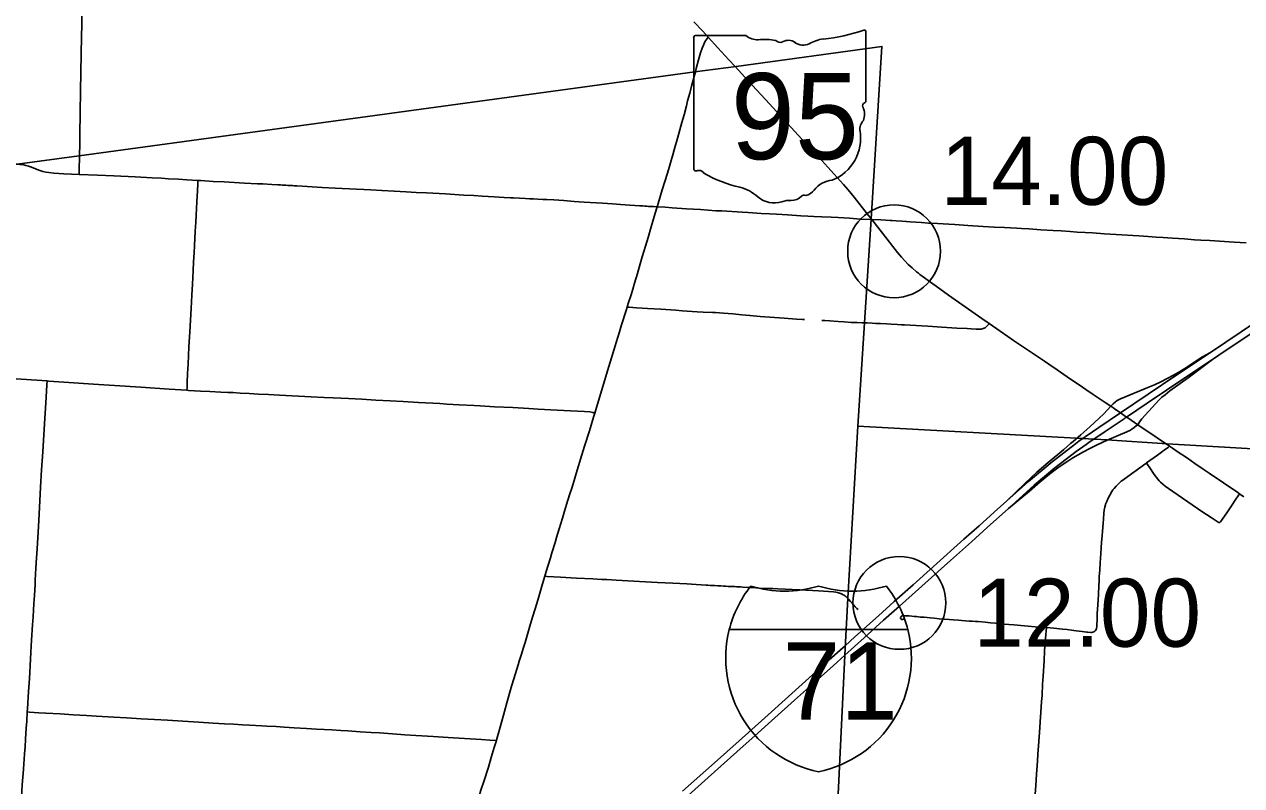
# Model space of a CAD drawing. Extents: x 1813937 to 1948437, y 826606 to 1022856.
# Drawn here: x 1890191 to 1909861, y 903518 to 915824 of the extents above; entities that cross this region are included whole.
import ezdxf

# ---------------------------------------------------------------- set-up
doc = ezdxf.new("R2010")
doc.units = 0
for name, color, linetype in [('Default', 7, 'Continuous'), ('GM_X_County_Road', 7, 'Continuous'), ('GM_X_Interchange_Ramps', 7, 'Continuous'), ('GM_X_Interstate_Route', 7, 'Continuous'), ('GM_X_Interstate_Shield', 7, 'Continuous'), ('GM_X_State_Route', 7, 'Continuous'), ('GM_X_State_Shield', 7, 'Continuous'), ('GM_X_Township', 7, 'Continuous'), ('GM_X_Township_Road', 7, 'Continuous')]:
    doc.layers.add(name, color=color, linetype=linetype)

msp = doc.modelspace()

# ---------------------------------------------------------------- linework, layer by layer
at = {"layer": 'Default'}
for centre in [(1904245, 912156), (1904331, 906472)]:
    msp.add_circle(centre, 750, dxfattribs=at)
at = {"layer": 'GM_X_County_Road'}
for points in [[(1901034, 915058), (1901047, 915109), (1901087, 915251), (1901119, 915361), (1901146, 915439), (1901163, 915485), (1901184, 915530), (1901200, 915558), (1901213, 915580), (1901223, 915594), (1901241, 915616)], [(1900416, 912874), (1900432, 912930), (1900499, 913150), (1900581, 913417), (1900609, 913511), (1900642, 913621), (1900670, 913715), (1900692, 913794), (1900751, 913999), (1900817, 914236), (1900852, 914363), (1900889, 914506), (1900909, 914585), (1900943, 914712), (1900972, 914823), (1901013, 914982), (1901034, 915058)], [(1899931, 911252), (1899950, 911310), (1899994, 911451), (1900023, 911545), (1900051, 911640), (1900097, 911797), (1900144, 911955), (1900176, 912065), (1900227, 912238), (1900269, 912379), (1900321, 912552), (1900386, 912773), (1900416, 912874)], [(1903887, 912667), (1904032, 912662), (1904114, 912658), (1904180, 912653), (1904212, 912651), (1904280, 912647), (1904372, 912640), (1904440, 912636), (1904445, 912636)], [(1904445, 912636), (1904506, 912632), (1904686, 912620), (1904800, 912612), (1904948, 912603), (1905128, 912592), (1905226, 912587), (1905439, 912573), (1905684, 912559), (1905864, 912548), (1906028, 912539), (1906224, 912528), (1906306, 912524), (1906421, 912516), (1906617, 912503), (1906813, 912493), (1906942, 912486), (1907089, 912475), (1907204, 912467), (1907334, 912460), (1907449, 912453), (1907645, 912440), (1907923, 912420), (1908103, 912409), (1908202, 912403), (1908349, 912393), (1908480, 912385), (1908594, 912377), (1908741, 912367), (1908938, 912355), (1909101, 912343), (1909199, 912338), (1909347, 912329), (1909740, 912304), (1909936, 912291)], [(1899410, 909541), (1899437, 909631), (1899637, 910291), (1899723, 910574), (1899756, 910684), (1899809, 910856), (1899843, 910966), (1899915, 911201), (1899931, 911252)], [(1887573, 910239), (1887606, 910237), (1887655, 910234), (1887786, 910225), (1887982, 910215), (1888179, 910203), (1888392, 910190), (1888850, 910163), (1889128, 910146), (1889390, 910131), (1889620, 910119), (1889849, 910105), (1890061, 910092), (1890307, 910076), (1890560, 910061)], [(1890238, 904709), (1890241, 904759), (1890260, 905038), (1890272, 905250), (1890290, 905561), (1890297, 905676), (1890309, 905872), (1890323, 906118), (1890332, 906249), (1890346, 906461), (1890354, 906592), (1890364, 906772), (1890368, 906838), (1890379, 907034), (1890389, 907199), (1890398, 907345), (1890418, 907705), (1890435, 908016), (1890455, 908343), (1890469, 908622), (1890488, 908916), (1890523, 909456), (1890533, 909620), (1890543, 909800), (1890556, 909996), (1890560, 910061)], [(1890560, 910061), (1890585, 910059), (1890831, 910042), (1891387, 910005), (1891649, 909988), (1892074, 909958), (1892532, 909928), (1892818, 909909)], [(1892818, 909909), (1892843, 909907), (1893040, 909896), (1893187, 909888), (1893367, 909879), (1893482, 909874), (1893563, 909871), (1893678, 909865), (1893825, 909857), (1893973, 909848), (1894136, 909840), (1894316, 909831), (1894824, 909804), (1895037, 909794), (1895184, 909787), (1895430, 909774), (1895643, 909764), (1895872, 909750), (1896101, 909737), (1896314, 909726), (1896560, 909712), (1896904, 909694), (1897018, 909687), (1897215, 909676), (1897460, 909664), (1897558, 909659), (1897788, 909644), (1898082, 909628), (1898344, 909614), (1898492, 909606), (1898803, 909589), (1899016, 909578), (1899245, 909566), (1899326, 909558), (1899375, 909552), (1899410, 909541)], [(1898602, 906902), (1898625, 906980), (1898691, 907200), (1898715, 907279), (1898769, 907451), (1898792, 907529), (1898835, 907671), (1898888, 907843), (1898921, 907953), (1898954, 908063), (1899002, 908220), (1899041, 908345), (1899085, 908487), (1899109, 908565), (1899201, 908863), (1899244, 909004), (1899322, 909255), (1899390, 909474), (1899410, 909541)], [(1908324, 908735), (1908499, 908861), (1908633, 908955), (1908672, 908985), (1908697, 909005)], [(1907661, 908057), (1907663, 908066), (1907680, 908112), (1907700, 908156), (1907729, 908215), (1907762, 908271), (1907780, 908298), (1907800, 908323), (1907833, 908360), (1907868, 908394), (1907916, 908438), (1907941, 908458), (1908021, 908516), (1908313, 908727), (1908324, 908735)], [(1908324, 908735), (1908339, 908712), (1908375, 908657), (1908450, 908550), (1908509, 908471), (1908529, 908446), (1908551, 908422), (1908587, 908389), (1908624, 908358), (1908677, 908320), (1909220, 907952), (1909369, 907850), (1909483, 907775), (1909492, 907771), (1909501, 907770)], [(1909501, 907770), (1909510, 907774), (1909517, 907781), (1909621, 907930), (1909695, 908039), (1909769, 908148), (1909805, 908204), (1909826, 908236)], [(1907528, 906301), (1907531, 906370), (1907541, 906518), (1907547, 906616), (1907554, 906746), (1907559, 906828), (1907561, 906894), (1907568, 907008), (1907576, 907122), (1907586, 907269), (1907593, 907368), (1907598, 907449), (1907607, 907563), (1907611, 907629), (1907621, 907759), (1907626, 907825), (1907635, 907922), (1907641, 907971), (1907651, 908019), (1907661, 908057)], [(1897819, 904246), (1897828, 904274), (1897881, 904463), (1897949, 904717), (1897988, 904859), (1898045, 905065), (1898068, 905143), (1898126, 905331), (1898170, 905473), (1898188, 905530), (1898219, 905629), (1898259, 905754), (1898282, 905833), (1898370, 906132), (1898408, 906258), (1898470, 906462), (1898498, 906556), (1898555, 906744), (1898597, 906886), (1898602, 906902)], [(1898602, 906902), (1898640, 906899), (1898853, 906887), (1899114, 906873), (1899376, 906859), (1899524, 906852), (1899605, 906848), (1899752, 906839), (1899851, 906833), (1900129, 906818), (1900423, 906802), (1900669, 906790), (1900898, 906778), (1901045, 906768), (1901208, 906759), (1901238, 906757), (1901272, 906755), (1901307, 906753), (1901351, 906751), (1901396, 906749), (1901444, 906746), (1901486, 906744), (1901525, 906742), (1901562, 906740), (1901601, 906738), (1901633, 906737), (1901669, 906735), (1901699, 906733), (1901736, 906732), (1901764, 906730), (1901800, 906728), (1901911, 906723), (1901960, 906720), (1902009, 906716), (1902058, 906713), (1902238, 906705), (1902287, 906703), (1902368, 906698), (1902483, 906692), (1902597, 906687), (1902728, 906681), (1903023, 906666), (1903187, 906658), (1903268, 906652), (1903301, 906647), (1903333, 906641), (1903364, 906631), (1903394, 906618), (1903423, 906603), (1903437, 906595), (1903451, 906586), (1903464, 906577), (1903477, 906567), (1903488, 906555), (1903502, 906540)], [(1903502, 906540), (1903509, 906531), (1903541, 906494), (1903585, 906445), (1903618, 906409), (1903644, 906384), (1903666, 906364)], [(1907041, 906040), (1907112, 906031), (1907188, 906023), (1907282, 906011), (1907362, 906001), (1907376, 905999), (1907425, 905995), (1907441, 905996), (1907458, 906000), (1907474, 906006), (1907488, 906015), (1907500, 906028), (1907508, 906043), (1907513, 906059), (1907519, 906092), (1907522, 906125), (1907525, 906193), (1907528, 906278), (1907528, 906301)], [(1906515, 903244), (1906534, 903523), (1906547, 903702), (1906561, 903915), (1906569, 904029), (1906578, 904160), (1906589, 904307), (1906599, 904455), (1906605, 904553), (1906616, 904700), (1906629, 904880), (1906635, 904978), (1906645, 905157), (1906653, 905288), (1906669, 905534), (1906678, 905697), (1906695, 905959), (1906701, 906017), (1906710, 906072)], [(1906710, 906072), (1906828, 906064), (1906968, 906049), (1907041, 906040)], [(1890074, 902387), (1890082, 902487), (1890099, 902716), (1890116, 902977), (1890125, 903108), (1890143, 903337), (1890157, 903533), (1890176, 903778), (1890182, 903877), (1890186, 903942), (1890195, 904040), (1890202, 904138), (1890210, 904269), (1890222, 904449), (1890231, 904562), (1890238, 904709)], [(1896982, 901567), (1896992, 901599), (1897000, 901626), (1897029, 901721), (1897078, 901878), (1897148, 902097), (1897213, 902300), (1897356, 902754), (1897446, 903035), (1897489, 903176), (1897540, 903349), (1897570, 903443), (1897615, 903583), (1897689, 903818), (1897736, 903976), (1897784, 904133), (1897819, 904246)]]:
    msp.add_lwpolyline(points, dxfattribs=at)
at = {"layer": 'GM_X_Interchange_Ramps'}
for points in [[(1909357, 910519), (1909230, 910449), (1908941, 910262), (1908844, 910201), (1908759, 910152), (1908658, 910097), (1908555, 910045), (1908451, 909997), (1908346, 909952), (1907996, 909810), (1907906, 909771), (1907862, 909749), (1907834, 909732), (1907821, 909722), (1907785, 909688), (1907746, 909651)], [(1908183, 909352), (1908218, 909406), (1908226, 909420), (1908247, 909445), (1908468, 909691), (1908525, 909750), (1908572, 909796), (1908623, 909838), (1908702, 909898), (1908997, 910109), (1909388, 910406)], [(1907746, 909651), (1907632, 909531), (1907406, 909319), (1907261, 909187), (1907138, 909080), (1907098, 909047), (1906988, 908953), (1906737, 908744), (1906554, 908585), (1906357, 908402), (1906069, 908123)], [(1906093, 907999), (1906433, 908281), (1906606, 908428), (1906758, 908553), (1906849, 908623), (1906928, 908681), (1907037, 908755), (1907134, 908817), (1907218, 908867), (1907304, 908915), (1907406, 908968), (1907524, 909025), (1907524, 909026), (1907689, 909100), (1908004, 909239), (1908063, 909267), (1908092, 909284), (1908119, 909303), (1908159, 909332), (1908183, 909352)]]:
    msp.add_lwpolyline(points, dxfattribs=at)
at = {"layer": 'GM_X_Interstate_Route'}
for points in [[(1908334, 909701), (1908957, 910122), (1909388, 910406), (1909597, 910545), (1910155, 910921), (1910468, 911132), (1910616, 911236), (1910775, 911351), (1910919, 911460), (1911087, 911591), (1911278, 911746), (1911323, 911783)], [(1900828, 903427), (1901390, 903931), (1901891, 904380), (1902208, 904664), (1902539, 904960), (1902929, 905310), (1903198, 905551), (1903418, 905748), (1903456, 905781), (1903613, 905924), (1903992, 906263), (1904248, 906493), (1904554, 906767), (1904883, 907063), (1905373, 907500), (1905617, 907719), (1905863, 907937), (1906069, 908123), (1906417, 908433), (1906800, 908754), (1907175, 909043), (1907231, 909086), (1907551, 909310), (1907901, 909545), (1908800, 910150), (1909357, 910519), (1910101, 911019)], [(1907979, 909461), (1908002, 909477), (1908334, 909701)], [(1907655, 909243), (1907962, 909449), (1907979, 909461)], [(1900863, 903312), (1901242, 903651), (1901706, 904067), (1902049, 904373), (1902318, 904614), (1902635, 904899), (1902879, 905118), (1903258, 905457), (1903447, 905627), (1903759, 905906), (1904075, 906192), (1904332, 906421), (1904638, 906695), (1904956, 906979), (1905154, 907156), (1905494, 907460), (1905751, 907689), (1906093, 907999), (1906509, 908375), (1906843, 908654), (1907186, 908918), (1907349, 909034), (1907413, 909080), (1907651, 909240), (1907655, 909243)]]:
    msp.add_lwpolyline(points, dxfattribs=at)
at = {"layer": 'GM_X_Interstate_Shield'}
for p, q in [((1901581, 906040), (1904467, 906040)), ((1904467, 906040), (1901581, 906040)), ((1904467, 906040), (1901581, 906040))]:
    msp.add_line(p, q, dxfattribs=at)
for centre, start, end in [((1903399, 905580), 141.669, 165.8066), ((1902476, 908537), 253.0091, 286.9909), ((1903572, 908537), 253.0091, 286.9909), ((1902649, 905580), 14.1934, 38.331), ((1903399, 905580), 165.8066, 258.463), ((1902649, 905580), 281.537, 14.1934)]:
    msp.add_arc(centre, 1875, start, end, dxfattribs=at)
at = {"layer": 'GM_X_State_Route'}
for points in [[(1901009, 915867), (1901154, 915711), (1901241, 915616), (1901398, 915445), (1901576, 915251), (1901675, 915144), (1901886, 914913), (1902230, 914538), (1902697, 914032), (1902952, 913754), (1903075, 913622), (1903176, 913514), (1903430, 913235), (1903505, 913148), (1903598, 913033), (1903810, 912761), (1903887, 912667), (1904056, 912447), (1904300, 912137), (1904362, 912062), (1904417, 912001), (1904475, 911943), (1904535, 911888), (1904609, 911823), (1904639, 911800)], [(1904639, 911800), (1904661, 911783), (1904873, 911629), (1904926, 911590), (1905125, 911446), (1905448, 911221), (1905662, 911069), (1905782, 910986), (1905958, 910864), (1906082, 910779)], [(1906082, 910779), (1906174, 910715), (1906338, 910606), (1906678, 910377), (1906746, 910331), (1906881, 910238), (1907044, 910128), (1907288, 909962), (1907344, 909924)], [(1907344, 909924), (1907464, 909842), (1907654, 909713), (1907746, 909651), (1907794, 909618)], [(1907794, 909618), (1907830, 909593), (1907833, 909591)], [(1907833, 909591), (1907901, 909545), (1908002, 909477), (1908021, 909464), (1908183, 909352), (1908223, 909325), (1908427, 909187), (1908549, 909105)], [(1908549, 909105), (1908658, 909031), (1908697, 909005), (1908745, 908972)], [(1908745, 908972), (1908821, 908921), (1908984, 908810), (1909105, 908726), (1909257, 908623)], [(1909257, 908623), (1909336, 908570), (1909566, 908413), (1909797, 908256), (1909826, 908236), (1909896, 908189)]]:
    msp.add_lwpolyline(points, dxfattribs=at)
at = {"layer": 'GM_X_State_Shield'}
for p, q in [((1901849, 915643), (1901034, 915643)), ((1903791, 914590), (1903791, 915696)), ((1901007, 915607), (1901007, 913494)), ((1903791, 914590), (1903791, 914590))]:
    msp.add_line(p, q, dxfattribs=at)
for centre, radius, start, end in [((1901038, 915611), 32.3, 98.1301, 188.1301), ((1902044, 915888), 313, 231.6195, 271.1119), ((1902799, 918524), 2953, 275.8445, 288.9065), ((1903760, 915700), 31, 351.8621, 97.738), ((1902147, 914457), 1123, 80.4867, 94.9883), ((1902402, 915622), 90.3, 219.7921, 297.1024), ((1902535, 915378), 188, 54.4667, 119.1411), ((1902777, 915713), 226, 233.8562, 294.8282), ((1903176, 914998), 594, 97.3462, 120.7689), ((1903784, 914509), 48, 107.944, 210.337), ((1903479, 914369), 288, 340.033, 23.6496), ((1903758, 914586), 33.2, 289.6038, 7.7341), ((1903902, 914127), 210, 136.8065, 186.9296), ((1902965, 913987), 739, 292.3089, 8.9858), ((1901039, 913489), 32.5, 171.9584, 258.3066), ((1901044, 913705), 248, 267.339, 280.6039), ((1901095, 913372), 89.5, 29.7484, 93.2717), ((1902225, 915270), 2132, 240.4129, 257.1985), ((1903276, 912900), 404, 94.4031, 142.5768), ((1901589, 912544), 667, 47.1842, 75.836), ((1902763, 913289), 239, 282.8732, 323.2771), ((1902311, 913361), 423, 230.7004, 286.2918), ((1902556, 912630), 348, 85.6951, 111.2099), ((1902586, 913203), 226, 268.777, 315.5493), ((1902791, 912998), 63.5, 65.7517, 132.6484)]:
    msp.add_arc(centre, radius, start, end, dxfattribs=at)
at = {"layer": 'GM_X_Township'}
for points in [[(1930733, 907844), (1927982, 907939), (1924001, 908161), (1918864, 908449), (1913461, 908761), (1908659, 909041), (1907683, 909106), (1907386, 909123), (1907188, 909134), (1903661, 909327), (1903767, 911000), (1903873, 912675), (1904049, 915466), (1901695, 915145), (1901024, 915054), (1891076, 913698), (1890078, 913562)], [(1929313, 880637), (1926519, 880798), (1923978, 880945), (1923826, 880954), (1918127, 881283), (1915079, 881414), (1912418, 881561), (1907482, 881867), (1902065, 882212), (1902276, 885593), (1902366, 887154), (1902378, 887248), (1902624, 890798), (1902935, 895772), (1903241, 901246), (1903453, 905734), (1903500, 906547), (1903661, 909327)]]:
    msp.add_lwpolyline(points, dxfattribs=at)
at = {"layer": 'GM_X_Township_Road'}
for points in [[(1891083, 913706), (1891086, 913892), (1891088, 914056), (1891093, 914384), (1891094, 914436), (1891095, 914497), (1891096, 914543), (1891097, 914601), (1891098, 914682), (1891099, 914738), (1891100, 914809), (1891101, 914872), (1891102, 914923), (1891103, 914982), (1891104, 915047), (1891105, 915121), (1891106, 915168), (1891107, 915220), (1891111, 915366), (1891119, 915841), (1891119, 915923), (1891121, 916152), (1891124, 916277)], [(1891075, 913399), (1891078, 913482), (1891083, 913679), (1891083, 913706)], [(1890021, 913560), (1890050, 913562), (1890083, 913563), (1890116, 913561), (1890149, 913558), (1890181, 913552), (1890213, 913545), (1890260, 913531), (1890306, 913514), (1890398, 913477), (1890444, 913461), (1890490, 913447), (1890538, 913435), (1890586, 913428), (1890668, 913421), (1890831, 913410), (1891075, 913399)], [(1891075, 913399), (1891374, 913387), (1891637, 913376), (1891980, 913358), (1892259, 913342), (1892406, 913335), (1892521, 913329), (1892684, 913321), (1892815, 913313), (1892997, 913301)], [(1892818, 909909), (1892820, 909952), (1892824, 910034), (1892830, 910182), (1892836, 910330), (1892850, 910609), (1892865, 910854), (1892886, 911232), (1892897, 911445), (1892907, 911625), (1892919, 911838), (1892927, 911986), (1892935, 912133), (1892942, 912248), (1892954, 912478), (1892963, 912625), (1892968, 912740), (1892981, 912953), (1892989, 913133), (1892995, 913248), (1892996, 913281), (1892997, 913301)], [(1892997, 913301), (1893044, 913298), (1893241, 913286), (1893421, 913277), (1893748, 913258), (1893961, 913247), (1894043, 913244), (1894190, 913236), (1894287, 913231), (1894330, 913228), (1894365, 913226), (1894390, 913225), (1894418, 913223), (1894449, 913221), (1894480, 913219), (1894524, 913217), (1894550, 913215), (1894594, 913212), (1894681, 913207), (1895003, 913188), (1895216, 913176), (1895789, 913147), (1895969, 913136), (1896165, 913127), (1896362, 913116), (1896525, 913108), (1896688, 913099), (1896999, 913082), (1897293, 913065), (1897457, 913055), (1897588, 913048), (1897784, 913035), (1897947, 913026), (1898045, 913020), (1898094, 913018), (1898192, 913013), (1898290, 913009), (1898356, 913006), (1898421, 913004), (1898486, 913000), (1898568, 912995), (1898633, 912991), (1898746, 912985), (1898910, 912974), (1899074, 912963), (1899237, 912951), (1899532, 912931), (1899695, 912921), (1899826, 912913), (1899973, 912902), (1900137, 912893), (1900187, 912888), (1900216, 912886), (1900250, 912884), (1900279, 912881), (1900300, 912880), (1900357, 912877), (1900406, 912874), (1900416, 912874)], [(1900416, 912874), (1900439, 912872), (1900545, 912867), (1900660, 912860), (1900889, 912844), (1901003, 912836), (1901118, 912829), (1901363, 912812), (1901461, 912807), (1901543, 912803), (1901707, 912793), (1901788, 912788), (1901886, 912781), (1902099, 912768), (1902230, 912761), (1902344, 912755), (1902524, 912743), (1902737, 912730), (1902851, 912723), (1902950, 912719), (1903080, 912715), (1903228, 912708), (1903342, 912701), (1903522, 912689), (1903702, 912676), (1903887, 912667)], [(1899931, 911252), (1899966, 911250), (1900081, 911242), (1900261, 911231), (1900475, 911218), (1900720, 911202), (1900819, 911195), (1900982, 911184), (1901064, 911179), (1901162, 911173), (1901310, 911167), (1901359, 911165), (1901490, 911155), (1901637, 911144), (1901784, 911131), (1901915, 911118), (1902079, 911104), (1902471, 911074), (1902668, 911060), (1902766, 911055), (1902799, 911054)], [(1903078, 911039), (1903127, 911038), (1903209, 911033), (1903339, 911022), (1903437, 911013), (1903551, 911006), (1903649, 911003), (1903731, 911001), (1903771, 910999)], [(1903771, 910999), (1903812, 910997), (1903893, 910994), (1903948, 910991), (1904026, 910987), (1904120, 910982), (1904200, 910978), (1904301, 910972), (1904365, 910969), (1904414, 910965), (1904691, 910949), (1904789, 910944), (1905017, 910930), (1905261, 910915), (1905424, 910906), (1905489, 910902), (1905571, 910898), (1905620, 910897), (1905653, 910899), (1905669, 910903), (1905684, 910908), (1905699, 910914), (1905714, 910921), (1905728, 910929), (1905751, 910949), (1905774, 910976), (1905782, 910986)], [(1904407, 906219), (1904395, 906208), (1904379, 906202), (1904364, 906204), (1904352, 906214), (1904348, 906230), (1904352, 906245), (1904363, 906257), (1904378, 906263), (1904393, 906265), (1904408, 906265), (1904420, 906265), (1904422, 906265), (1904461, 906264), (1904489, 906262), (1904531, 906259), (1904572, 906255), (1904606, 906250), (1904671, 906244), (1904731, 906239), (1904826, 906230), (1904891, 906223), (1904973, 906216), (1905137, 906204), (1905202, 906199), (1905284, 906193), (1905338, 906188), (1905400, 906183), (1905456, 906179), (1905507, 906175), (1905559, 906172), (1905606, 906169), (1905715, 906159), (1905803, 906152), (1905885, 906145), (1905933, 906139), (1906031, 906131), (1906097, 906125), (1906178, 906118), (1906522, 906087), (1906669, 906075), (1906710, 906072)], [(1890238, 904709), (1890277, 904708), (1890425, 904698), (1890539, 904691), (1890769, 904678), (1890982, 904664), (1891195, 904654), (1891359, 904643), (1891637, 904627), (1891850, 904614), (1892079, 904600), (1892292, 904589), (1892505, 904577), (1892751, 904563), (1893013, 904546), (1893242, 904530), (1893423, 904520), (1893570, 904512), (1893717, 904502), (1893832, 904496), (1894029, 904485), (1894111, 904480), (1894258, 904473), (1894389, 904464), (1894552, 904454), (1894749, 904444), (1894913, 904434), (1895159, 904420), (1895306, 904410), (1895421, 904402), (1895617, 904387), (1895797, 904377), (1895928, 904370), (1896141, 904357), (1896337, 904342), (1896517, 904330), (1896616, 904324), (1896796, 904314), (1897042, 904297), (1897304, 904281), (1897578, 904262), (1897713, 904254), (1897819, 904246)]]:
    msp.add_lwpolyline(points, dxfattribs=at)

# ---------------------------------------------------------------- texts
at = {"layer": 'Default'}
for s, p in [('14.00', (1904995, 912906)), ('12.00', (1905525, 905764))]:
    msp.add_text(s, height=1100, dxfattribs=at).set_placement(p)
at = {"layer": 'GM_X_Interstate_Shield'}
msp.add_text('71', height=1250, dxfattribs=at).set_placement((1902447, 904587))
at = {"layer": 'GM_X_State_Shield'}
msp.add_text('95', height=1392.2, dxfattribs=at).set_placement((1901607, 913643))

doc.saveas('drawing.dxf')
